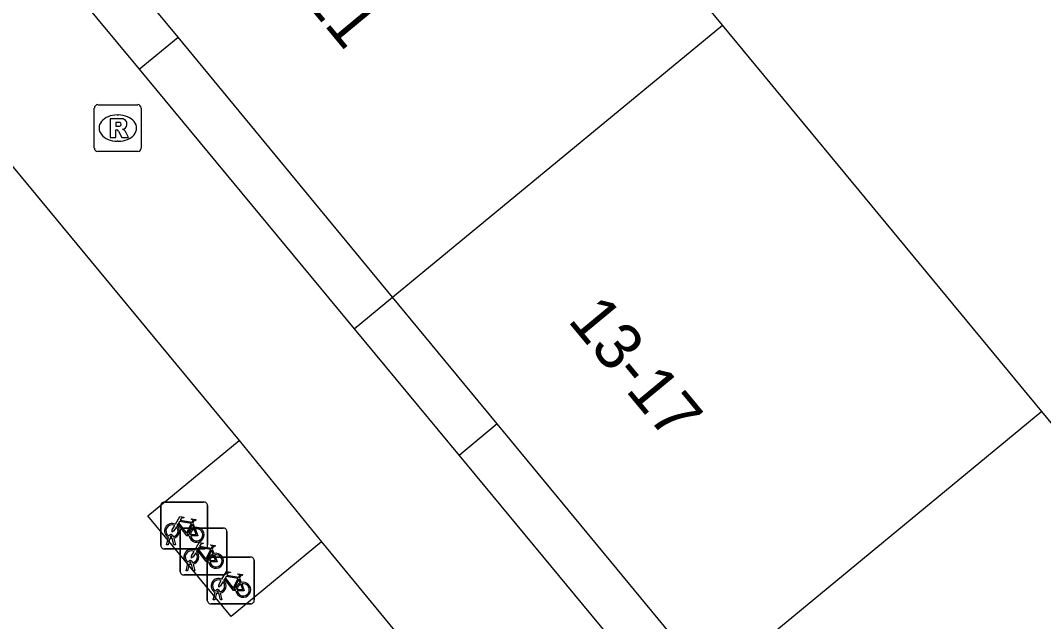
# Model space of a CAD drawing. Extents: x 162347 to 162868, y 381221 to 381813.
# Drawn here: x 162471.84 to 162493.66, y 381706.2 to 381719.03 of the extents above; entities that cross this region are included whole.
import ezdxf

# ---------------------------------------------------------------- set-up
doc = ezdxf.new("R2010")
doc.units = 0
for name, color, linetype in [('IMGEO_Fietsenrek', 7, 'Continuous'), ('IMGEO_Pand', 7, 'Continuous'), ('IMGEO_Pand_nummerreeks', 7, 'Continuous'), ('IMGEO_Rioolput', 7, 'Continuous'), ('IMGEO_Voetpad_open', 7, 'Continuous')]:
    doc.layers.add(name, color=color, linetype=linetype)

msp = doc.modelspace()

# ---------------------------------------------------------------- linework, layer by layer
at = {"layer": 'IMGEO_Fietsenrek'}
for p, q in [((162474.834, 381707.825), (162474.834, 381708.666)), ((162474.834, 381708.666), (162474.834, 381707.825)), ((162474.909, 381708.75), (162475.75, 381708.75)), ((162475.75, 381708.75), (162474.909, 381708.75)), ((162475.834, 381708.675), (162475.834, 381707.834)), ((162475.834, 381707.834), (162475.834, 381708.675)), ((162475.322, 381708.196), (162476.163, 381708.196)), ((162476.163, 381708.196), (162475.322, 381708.196)), ((162475.521, 381708.299), (162475.557, 381708.204)), ((162476.247, 381708.121), (162476.247, 381707.28)), ((162476.247, 381707.28), (162476.247, 381708.121)), ((162474.961, 381707.834), (162475, 381707.994)), ((162475.03, 381707.982), (162474.995, 381707.834)), ((162475.072, 381708.006), (162475.071, 381708.01)), ((162475.113, 381707.834), (162475.079, 381707.976)), ((162475.103, 381708.017), (162475.104, 381708.01)), ((162475.111, 381707.98), (162475.146, 381707.834)), ((162475.247, 381707.271), (162475.247, 381708.112)), ((162475.247, 381708.112), (162475.247, 381707.271)), ((162475.759, 381707.75), (162474.918, 381707.75)), ((162474.918, 381707.75), (162475.759, 381707.75)), ((162474.995, 381707.834), (162474.961, 381707.834)), ((162475.146, 381707.834), (162475.113, 381707.834)), ((162475.934, 381707.745), (162475.97, 381707.65)), ((162475.516, 381707.463), (162475.517, 381707.456)), ((162475.828, 381706.652), (162475.828, 381707.493)), ((162475.828, 381707.493), (162475.828, 381706.652)), ((162475.903, 381707.577), (162476.744, 381707.577)), ((162476.744, 381707.577), (162475.903, 381707.577)), ((162476.828, 381707.502), (162476.828, 381706.661)), ((162476.828, 381706.661), (162476.828, 381707.502)), ((162475.374, 381707.28), (162475.413, 381707.44)), ((162475.408, 381707.28), (162475.374, 381707.28)), ((162475.443, 381707.428), (162475.408, 381707.28)), ((162475.485, 381707.452), (162475.484, 381707.456)), ((162475.526, 381707.28), (162475.492, 381707.422)), ((162475.524, 381707.426), (162475.559, 381707.28)), ((162475.559, 381707.28), (162475.526, 381707.28)), ((162476.172, 381707.196), (162475.331, 381707.196)), ((162475.331, 381707.196), (162476.172, 381707.196)), ((162476.515, 381707.126), (162476.551, 381707.031)), ((162475.955, 381706.661), (162475.994, 381706.821)), ((162476.024, 381706.809), (162475.989, 381706.661)), ((162476.066, 381706.833), (162476.065, 381706.837)), ((162476.107, 381706.661), (162476.073, 381706.803)), ((162476.097, 381706.844), (162476.098, 381706.837)), ((162476.105, 381706.807), (162476.14, 381706.661)), ((162475.989, 381706.661), (162475.955, 381706.661)), ((162476.14, 381706.661), (162476.107, 381706.661)), ((162476.753, 381706.577), (162475.912, 381706.577)), ((162475.912, 381706.577), (162476.753, 381706.577))]:
    msp.add_line(p, q, dxfattribs=at)
for points in [[(162475.147, 381708.276), (162475.242, 381708.44), (162475.328, 381708.426), (162475.33, 381708.417), (162475.274, 381708.406), (162475.247, 381708.361), (162475.503, 381708.32)], [(162475.49, 381708.295), (162475.233, 381708.336), (162475.216, 381708.307), (162475.383, 381708.087), (162475.49, 381708.295)], [(162475.503, 381708.32), (162475.528, 381708.369), (162475.522, 381708.373), (162475.499, 381708.377), (162475.487, 381708.384), (162475.486, 381708.387), (162475.488, 381708.392), (162475.583, 381708.377), (162475.585, 381708.367), (162475.575, 381708.354), (162475.563, 381708.348), (162475.549, 381708.354), (162475.521, 381708.299)], [(162475.168, 381708.224), (162475.116, 381708.134), (162475.076, 381708.109), (162475.077, 381708.156), (162475.132, 381708.25)], [(162475.443, 381708.032), (162475.393, 381708.032), (162475.202, 381708.283), (162475.183, 381708.251)], [(162475.538, 381708.197), (162475.508, 381708.274), (162475.399, 381708.056), (162475.442, 381708.056)], [(162475.472, 381708.056), (162475.592, 381708.055), (162475.548, 381708.169)], [(162475.568, 381708.176), (162475.623, 381708.031), (162475.473, 381708.031)], [(162475.581, 381707.67), (162475.529, 381707.58), (162475.489, 381707.555), (162475.49, 381707.602), (162475.545, 381707.696)], [(162475.56, 381707.722), (162475.655, 381707.886), (162475.741, 381707.872), (162475.743, 381707.863), (162475.687, 381707.852), (162475.66, 381707.807), (162475.916, 381707.766)], [(162475.856, 381707.478), (162475.806, 381707.478), (162475.615, 381707.729), (162475.596, 381707.697)], [(162475.903, 381707.741), (162475.646, 381707.782), (162475.629, 381707.753), (162475.796, 381707.533), (162475.903, 381707.741)], [(162475.951, 381707.643), (162475.921, 381707.72), (162475.812, 381707.502), (162475.855, 381707.502)], [(162475.916, 381707.766), (162475.941, 381707.815), (162475.935, 381707.819), (162475.912, 381707.823), (162475.9, 381707.83), (162475.899, 381707.833), (162475.901, 381707.838), (162475.996, 381707.823), (162475.998, 381707.813), (162475.988, 381707.8), (162475.976, 381707.794), (162475.962, 381707.8), (162475.934, 381707.745)], [(162475.885, 381707.502), (162476.005, 381707.501), (162475.961, 381707.615)], [(162475.981, 381707.622), (162476.036, 381707.477), (162475.886, 381707.477)], [(162476.141, 381707.103), (162476.236, 381707.267), (162476.322, 381707.253), (162476.324, 381707.244), (162476.268, 381707.233), (162476.241, 381707.188), (162476.497, 381707.147)], [(162476.162, 381707.051), (162476.11, 381706.961), (162476.07, 381706.936), (162476.071, 381706.983), (162476.126, 381707.077)], [(162476.437, 381706.859), (162476.387, 381706.859), (162476.196, 381707.11), (162476.177, 381707.078)], [(162476.484, 381707.122), (162476.227, 381707.163), (162476.21, 381707.134), (162476.377, 381706.914), (162476.484, 381707.122)], [(162476.532, 381707.024), (162476.502, 381707.101), (162476.393, 381706.883), (162476.436, 381706.883)], [(162476.497, 381707.147), (162476.522, 381707.196), (162476.516, 381707.2), (162476.493, 381707.204), (162476.481, 381707.211), (162476.48, 381707.214), (162476.482, 381707.219), (162476.577, 381707.204), (162476.579, 381707.194), (162476.569, 381707.181), (162476.557, 381707.175), (162476.543, 381707.181), (162476.515, 381707.126)], [(162476.466, 381706.883), (162476.586, 381706.882), (162476.542, 381706.996)], [(162476.562, 381707.003), (162476.617, 381706.858), (162476.467, 381706.858)]]:
    msp.add_lwpolyline(points, dxfattribs=at)
for centre, radius, start, end in [((162474.912, 381708.672), 0.0779, 92.4484, 184.2845), ((162474.912, 381708.672), 0.0779, 92.4484, 184.2845), ((162475.756, 381708.672), 0.0779, 2.4484, 94.2845), ((162475.756, 381708.672), 0.0779, 2.4484, 94.2845), ((162475.074, 381708.135), 0.159, 62.6766, 242.1369), ((162475.074, 381708.135), 0.129, 63.3192, 238.903), ((162475.074, 381708.135), 0.129, 283.6043, 43.4302), ((162475.074, 381708.135), 0.159, 283.5766, 46.6042), ((162475.325, 381708.118), 0.0779, 92.4484, 184.2845), ((162475.325, 381708.118), 0.0779, 92.4484, 184.2845), ((162475.601, 381708.051), 0.159, 113.3408, 178.3217), ((162475.601, 381708.051), 0.159, 187.0065, 105.7708), ((162475.601, 381708.051), 0.129, 113.923, 177.9556), ((162475.601, 381708.051), 0.129, 188.6715, 104.5883), ((162476.169, 381708.118), 0.0779, 2.4484, 94.2845), ((162476.169, 381708.118), 0.0779, 2.4484, 94.2845), ((162475.054, 381708.006), 0.0499, 12.8025, 158.6934), ((162475.074, 381708.135), 0.159, 253.9967, 271.7867), ((162475.054, 381708.006), 0.0174, 12.8025, 163.4502), ((162475.074, 381708.135), 0.129, 253.415, 269.0204), ((162474.912, 381707.828), 0.0779, 182.4484, 274.2845), ((162474.912, 381707.828), 0.0779, 182.4484, 274.2845), ((162475.487, 381707.581), 0.159, 62.6766, 242.1369), ((162475.487, 381707.581), 0.129, 63.3192, 238.903), ((162475.487, 381707.581), 0.159, 283.5766, 46.6042), ((162475.756, 381707.828), 0.0779, 272.4484, 4.2845), ((162475.756, 381707.828), 0.0779, 272.4484, 4.2845), ((162475.467, 381707.452), 0.0499, 12.8025, 158.6934), ((162475.467, 381707.452), 0.0174, 12.8025, 163.4502), ((162475.487, 381707.581), 0.129, 283.6043, 43.4302), ((162475.906, 381707.499), 0.0779, 92.4484, 184.2845), ((162475.906, 381707.499), 0.0779, 92.4484, 184.2845), ((162476.014, 381707.497), 0.159, 113.3408, 178.3217), ((162476.014, 381707.497), 0.159, 187.0065, 105.7708), ((162476.014, 381707.497), 0.129, 113.923, 177.9556), ((162476.014, 381707.497), 0.129, 188.6715, 104.5883), ((162476.75, 381707.499), 0.0779, 2.4484, 94.2845), ((162476.75, 381707.499), 0.0779, 2.4484, 94.2845), ((162475.325, 381707.274), 0.0779, 182.4484, 274.2845), ((162475.325, 381707.274), 0.0779, 182.4484, 274.2845), ((162475.487, 381707.581), 0.159, 253.9967, 271.7867), ((162475.487, 381707.581), 0.129, 253.415, 269.0204), ((162476.169, 381707.274), 0.0779, 272.4484, 4.2845), ((162476.169, 381707.274), 0.0779, 272.4484, 4.2845), ((162476.068, 381706.962), 0.159, 62.6766, 242.1369), ((162476.068, 381706.962), 0.129, 63.3192, 238.903), ((162476.068, 381706.962), 0.129, 283.6043, 43.4302), ((162476.068, 381706.962), 0.159, 283.5766, 46.6042), ((162476.595, 381706.878), 0.159, 113.3408, 178.3217), ((162476.595, 381706.878), 0.159, 187.0065, 105.7708), ((162476.048, 381706.833), 0.0499, 12.8025, 158.6934), ((162476.068, 381706.962), 0.159, 253.9967, 271.7867), ((162476.048, 381706.833), 0.0174, 12.8025, 163.4502), ((162476.068, 381706.962), 0.129, 253.415, 269.0204), ((162476.595, 381706.878), 0.129, 113.923, 177.9556), ((162476.595, 381706.878), 0.129, 188.6715, 104.5883), ((162475.906, 381706.655), 0.0779, 182.4484, 274.2845), ((162475.906, 381706.655), 0.0779, 182.4484, 274.2845), ((162476.75, 381706.655), 0.0779, 272.4484, 4.2845), ((162476.75, 381706.655), 0.0779, 272.4484, 4.2845)]:
    msp.add_arc(centre, radius, start, end, dxfattribs=at)
at = {"layer": 'IMGEO_Pand'}
for points in [[(162486.816, 381718.931), (162480.005, 381727.183)], [(162475.203, 381718.673), (162472.969, 381721.38)], [(162479.778, 381713.127), (162486.816, 381718.931)], [(162493.628, 381710.68), (162486.816, 381718.931)], [(162479.778, 381713.127), (162475.203, 381718.673)], [(162482.012, 381710.419), (162479.778, 381713.127)], [(162493.628, 381710.68), (162486.587, 381704.873)], [(162500.056, 381702.892), (162493.628, 381710.68)], [(162486.587, 381704.873), (162482.012, 381710.419)]]:
    msp.add_lwpolyline(points, dxfattribs=at)
at = {"layer": 'IMGEO_Rioolput'}
for p, q in [((162473.418, 381716.307), (162473.418, 381717.159)), ((162473.493, 381717.233), (162474.345, 381717.233)), ((162474.419, 381717.159), (162474.419, 381716.307)), ((162473.906, 381717.013), (162473.931, 381717.013)), ((162473.929, 381716.453), (162473.904, 381716.453)), ((162474.345, 381716.233), (162473.493, 381716.233))]:
    msp.add_line(p, q, dxfattribs=at)
for points in [[(162473.418, 381716.307), (162473.418, 381717.159)], [(162473.493, 381717.233), (162474.345, 381717.233)], [(162474.419, 381717.159), (162474.419, 381716.307)], [(162474.007, 381716.931), (162473.755, 381716.933), (162473.755, 381716.533)], [(162473.933, 381716.852), (162473.879, 381716.852), (162473.879, 381716.771)], [(162473.755, 381716.533), (162473.879, 381716.533), (162473.879, 381716.695), (162473.89, 381716.695)], [(162473.879, 381716.771), (162473.931, 381716.771)], [(162473.937, 381716.666), (162474.008, 381716.533), (162474.148, 381716.533), (162474.083, 381716.659)], [(162474.345, 381716.233), (162473.493, 381716.233)]]:
    msp.add_lwpolyline(points, dxfattribs=at)
for centre, radius, start, end in [((162473.495, 381717.157), 0.0765, 91.552, 178.448), ((162473.495, 381717.157), 0.0765, 91.552, 178.448), ((162474.343, 381717.157), 0.0765, 1.552, 88.448), ((162474.343, 381717.157), 0.0765, 1.552, 88.448), ((162473.939, 381716.756), 0.0964, 77.0061, 93.1865), ((162473.953, 381716.813), 0.0378, 276.6634, 79.6772), ((162474.006, 381716.821), 0.109, 350.3612, 89.416), ((162473.889, 381716.642), 0.0533, 26.0293, 88.6989), ((162473.915, 381716.96), 0.19, 274.7715, 282.9687), ((162474.004, 381716.821), 0.112, 277.5842, 350.9817), ((162473.988, 381716.606), 0.108, 29.5134, 73.7905), ((162473.495, 381716.309), 0.0765, 181.552, 268.448), ((162473.495, 381716.309), 0.0765, 181.552, 268.448), ((162474.343, 381716.309), 0.0765, 271.552, 358.448), ((162474.343, 381716.309), 0.0765, 271.552, 358.448)]:
    msp.add_arc(centre, radius, start, end, dxfattribs=at)
for centre, major_axis, ratio, start_param, end_param in [((162473.905, 381716.733), (-0.387, 0.002), 0.722429, 4.712389, 7.853982), ((162473.93, 381716.733), (-0.39, 0.002), 0.717154, 1.570796, 4.712389)]:
    msp.add_ellipse(centre, major_axis=major_axis, ratio=ratio, start_param=start_param, end_param=end_param, dxfattribs=at)
at = {"layer": 'IMGEO_Voetpad_open'}
for points in [[(162472.137, 381720.694), (162474.375, 381717.99)], [(162474.375, 381717.99), (162475.203, 381718.673)], [(162474.375, 381717.99), (162478.958, 381712.451)], [(162471.549, 381716.061), (162476.506, 381710.061)], [(162478.958, 381712.451), (162479.778, 381713.127)], [(162478.958, 381712.451), (162481.196, 381709.747)], [(162482.012, 381710.419), (162481.196, 381709.747)], [(162478.262, 381707.898), (162476.338, 381706.309), (162474.559, 381708.455), (162476.506, 381710.061)], [(162476.506, 381710.061), (162478.262, 381707.898)], [(162481.196, 381709.747), (162485.78, 381704.207)], [(162478.262, 381707.898), (162483.232, 381701.86)]]:
    msp.add_lwpolyline(points, dxfattribs=at)

# ---------------------------------------------------------------- texts
at = {"layer": 'IMGEO_Pand_nummerreeks'}
for s, p in [('7-11', (162477.068, 381720.427)), ('13-17', (162483.496, 381712.622))]:
    msp.add_text(s, height=1, rotation=309.6599, dxfattribs=at).set_placement(p)

doc.saveas('drawing.dxf')
